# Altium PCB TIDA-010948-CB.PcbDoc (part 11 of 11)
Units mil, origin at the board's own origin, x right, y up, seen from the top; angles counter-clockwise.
Board outline 8100 x 8400 mil, 8 copper layers (L01 - TOP, L02 - GND, L03 - SIG, L04 - GND, L05 - PWR, L06 - SIG, L07 - GND, L08 - BOTTOM), stack 59.656 mil thick; 711 components, 572 nets, 2646 pads, 1325 vias.
Unrouted connection lines stored in the file: 988.
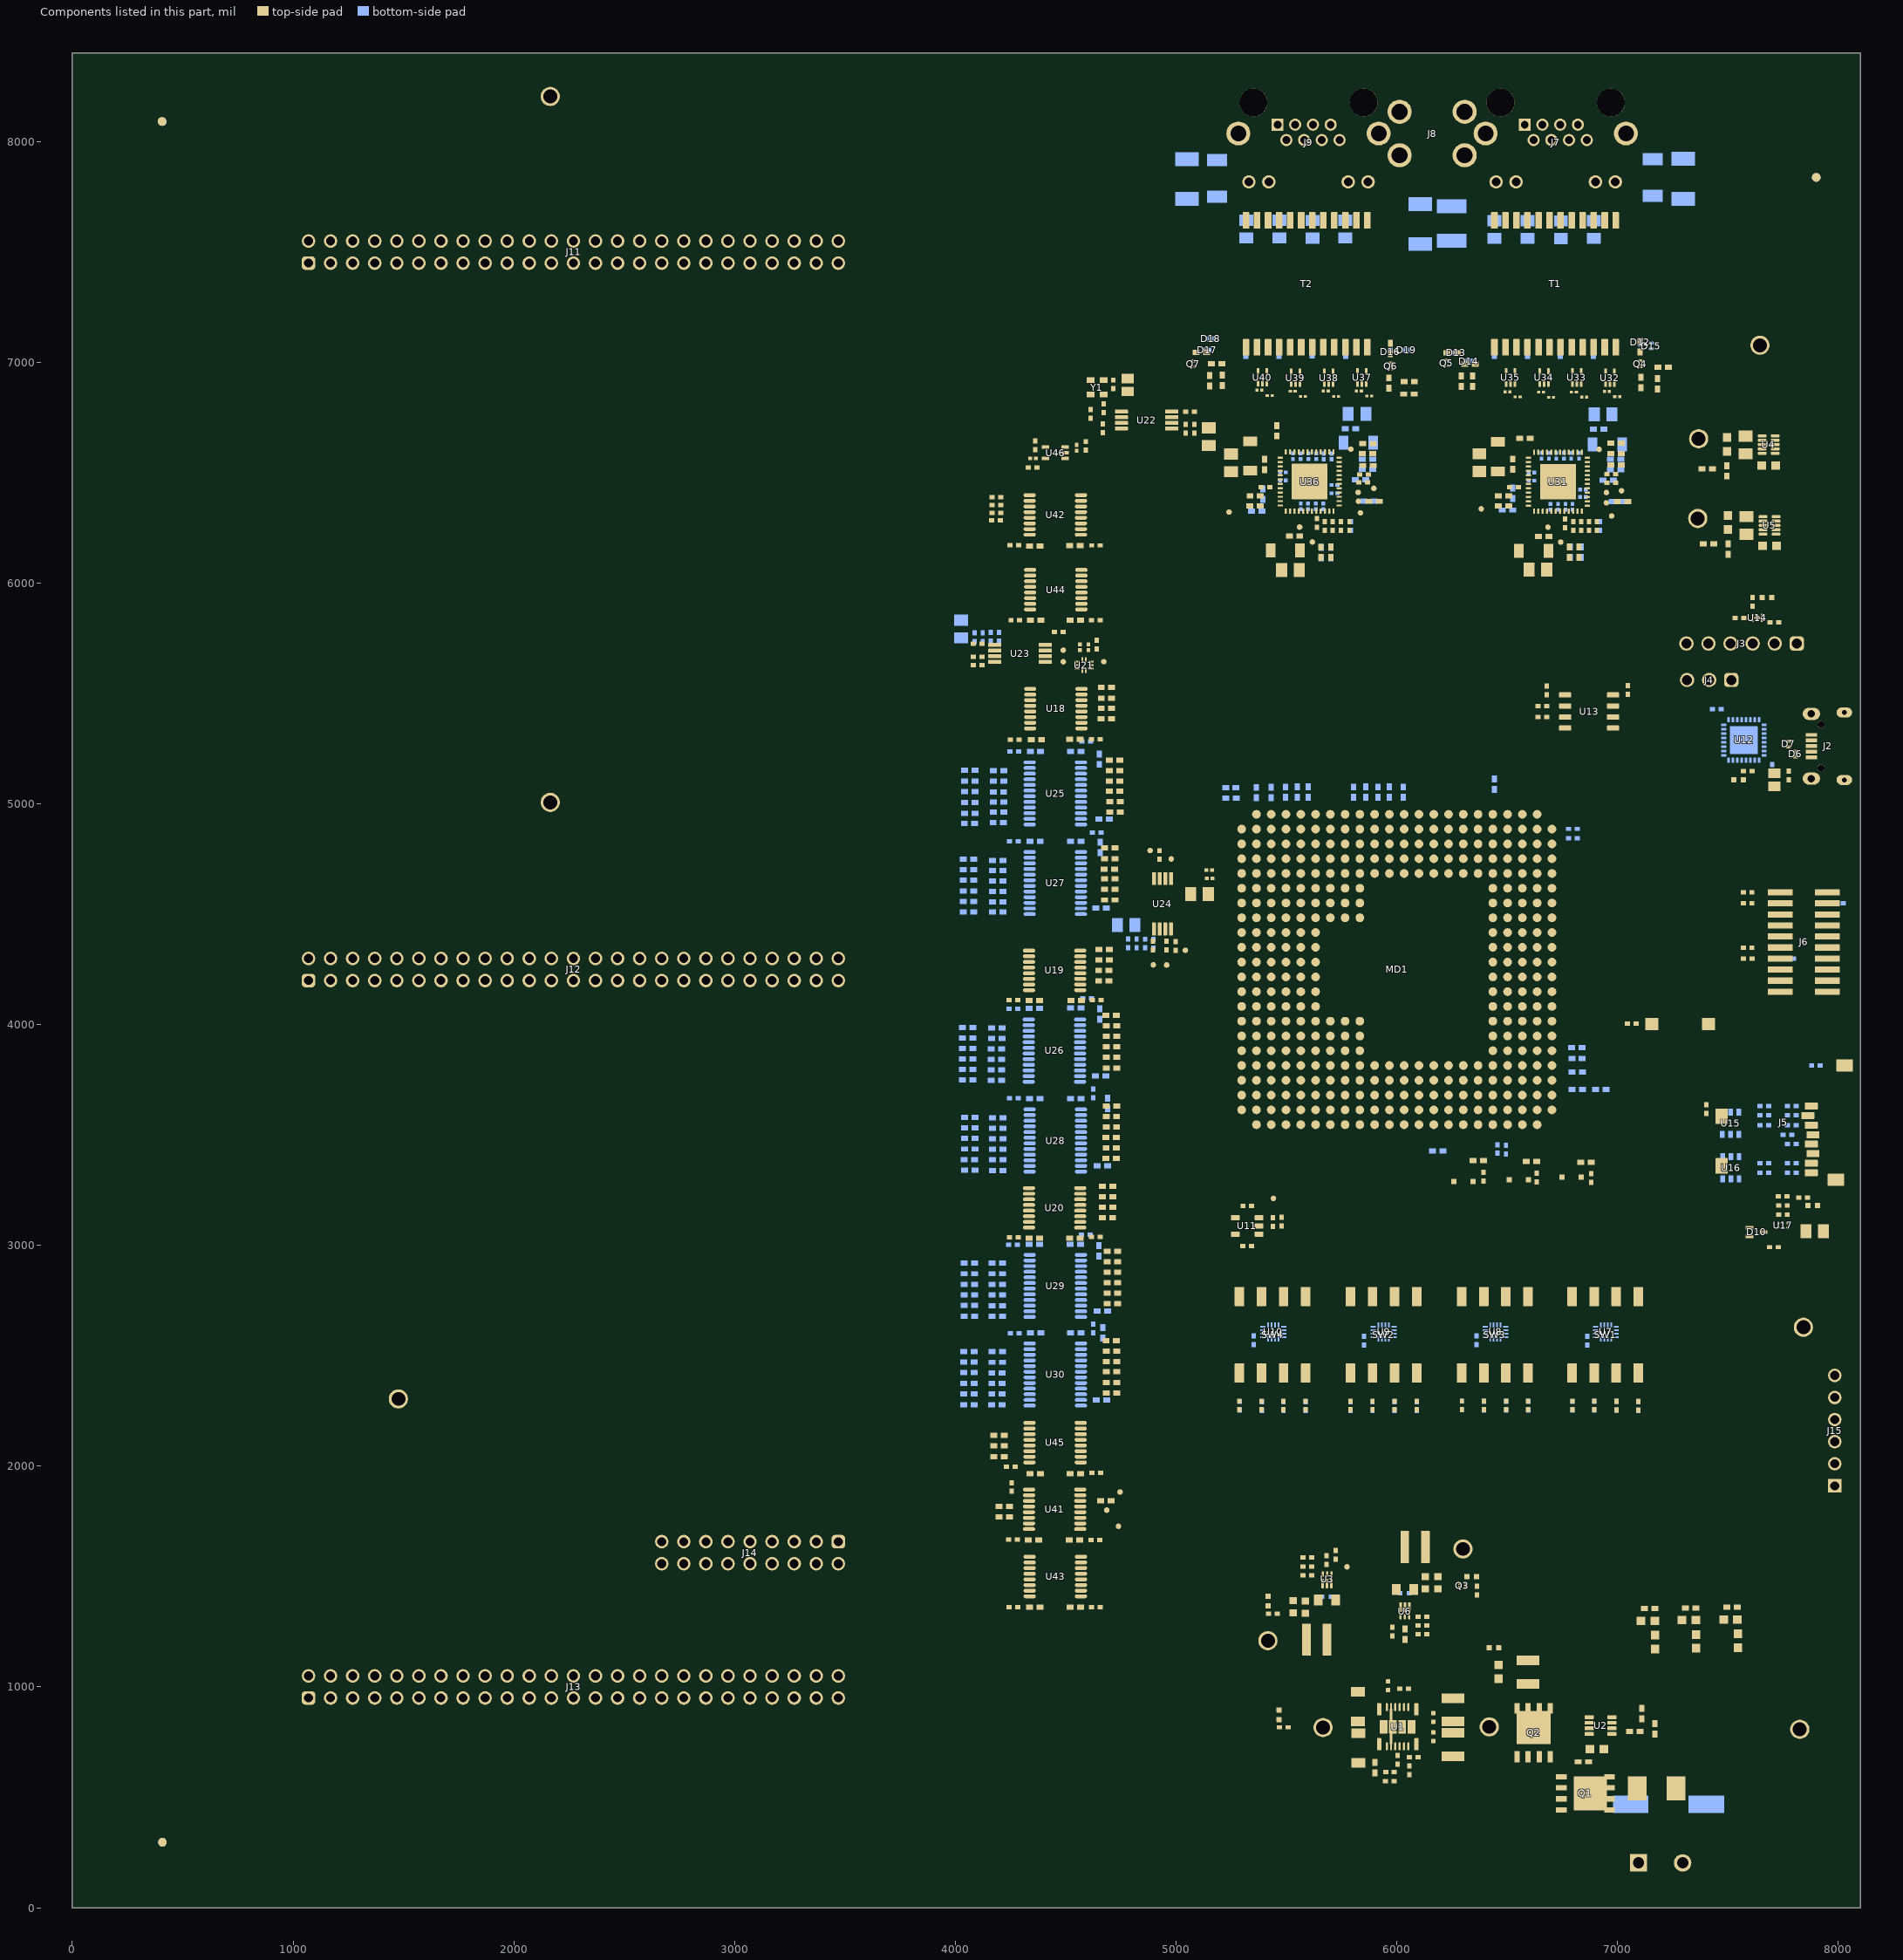
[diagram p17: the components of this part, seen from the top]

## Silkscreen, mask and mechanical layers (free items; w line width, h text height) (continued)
M12 Stackup:
  drawing of 516 lines, arcs and shapes, not listed
  text "Z0 = 50R" at 10519.74,6538.63 h35
  text "Zdiff = 100R" at 11169.35,6538.63 h35
  text "TYPE" at 9988.24,6499.26 h35
  text "line width" at 10480.37,6459.89 h35
  text "line width / space" at 11070.92,6459.89 h35
  text "LAYER 1" at 9948.87,6341.78 h35
  text "5.25 MIL" at 10519.74,6341.78 h35
  text "3.50 / 9.0 MIL" at 11149.66,6341.78 h35
  text "LAYER 2" at 9948.87,6223.67 h35
  text "---REF---" at 10480.37,6223.67 h35
  text "---REF---" at 11228.4,6223.67 h35
  text "LAYER 3" at 9948.87,6105.56 h35
  text "4.25 MIL" at 10519.74,6105.56 h35
  text "4.00 / 8.0 MIL" at 11149.66,6105.56 h35
  text "LAYER 4" at 9948.87,5987.45 h35
  text "---REF---" at 10480.37,5987.45 h35
  text "-" at 11385.88,5987.45 h35
  text "LAYER 5" at 9948.87,5869.34 h35
  text "-" at 10634.01,5869.08 h35
  text "-" at 11385.88,5869.34 h35
  text "4.25 MIL" at 10515.74,5753.06 h35
  text "LAYER 6" at 9948.87,5751.23 h35
  text "-" at 11385.88,5751.23 h35
  text "Layer" at 9901.87,5344.5 h35
  text "Name" at 10141.32,5344.5 h35
  text "Material" at 10684,5344.5 h35
  text "Thickness" at 12200.54,5344.5 h35
  text "Constant" at 12579.94,5344.5 h35
  text "Board Layer Stack" at 12912.69,5344.5 h35
  text "Top Overlay" at 10141.32,5274.5 h35
  text "Top Solder" at 10141.32,5204.5 h35
  text "Solder Resist" at 10684,5204.5 h35
  text "0.90mil" at 12200.54,5204.5 h35
  text "4.1" at 12579.94,5204.5 h35
  text "1" at 9901.87,5134.5 h35
  text "L01 - TOP" at 10141.32,5134.5 h35
  text "1.38mil" at 12200.54,5134.5 h35
  text "Dielectric 1" at 10141.32,5064.5 h35
  text "1080-FR4 370" at 10684,5064.5 h35
  text "2.80mil" at 12200.54,5064.5 h35
  text "4.1" at 12579.94,5064.5 h35
  text "2" at 9901.87,4994.5 h35
  text "L02 - GND" at 10141.32,4994.5 h35
  text "CF-004" at 10684,4994.5 h35
  text "1.20mil" at 12200.54,4994.5 h35
  text "Dielectric 2" at 10141.32,4924.5 h35
  text "FR4 370" at 10684,4924.5 h35
  text "5.00mil" at 12200.54,4924.5 h35
  text "4.1" at 12579.94,4924.5 h35
  text "3" at 9901.87,4854.5 h35
  text "L03 - SIG" at 10141.32,4854.5 h35
  text "1.20mil" at 12200.54,4854.5 h35
  text "Dielectric 3" at 10141.32,4784.5 h35
  text "1080-FR4 370 + 2116-FR4 370 + 1080-FR4 370" at 10684,4784.5 h35
  text "9.80mil" at 12200.54,4784.5 h35
  text "4.1" at 12579.94,4784.5 h35
  text "4" at 9901.87,4714.5 h35
  text "L04 - GND" at 10141.32,4714.5 h35
  text "1.20mil" at 12200.54,4714.5 h35
  text "Dielectric 4" at 10141.32,4644.5 h35
  text "FR4 370" at 10684,4644.5 h35
  text "14.50mil" at 12200.54,4644.5 h35
  text "4.4" at 12579.94,4644.5 h35
  text "5" at 9901.87,4574.5 h35
  text "L05 - PWR" at 10141.32,4574.5 h35
  text "1.20mil" at 12200.54,4574.5 h35
  text "Dielectric 5" at 10141.32,4504.5 h35
  text "1080-FR4 370 + 2116-FR4 370 + 1080-FR4 370" at 10684,4504.5 h35
  text "9.80mil" at 12200.54,4504.5 h35
  text "4.1" at 12579.94,4504.5 h35
  text "6" at 9901.87,4434.5 h35
  text "L06 - SIG" at 10141.32,4434.5 h35
  text "1.20mil" at 12200.54,4434.5 h35
  text "Dielectric 6" at 10141.32,4364.5 h35
  text "FR4 370" at 10684,4364.5 h35
  text "5.00mil" at 12200.54,4364.5 h35
  text "4.1" at 12579.94,4364.5 h35
  text "7" at 9901.87,4294.5 h35
  text "L07 - GND" at 10141.32,4294.5 h35
  text "CF-004" at 10684,4294.5 h35
  text "1.20mil" at 12200.54,4294.5 h35
  text "Dielectric 7" at 10141.32,4224.5 h35
  text "1080-FR4 370" at 10684,4224.5 h35
  text "2.80mil" at 12200.54,4224.5 h35
  text "4.1" at 12579.94,4224.5 h35
  text "8" at 9901.87,4154.5 h35
  text "L08 - BOTTOM" at 10141.32,4154.5 h35
  text "1.38mil" at 12200.54,4154.5 h35
  text "Bottom Solder" at 10141.32,4084.5 h35
  text "Solder Resist" at 10684,4084.5 h35
  text "0.90mil" at 12200.54,4084.5 h35
  text "4.1" at 12579.94,4084.5 h35
  text "Bottom Overlay" at 10141.32,4014.5 h35
  text ".Layer_Name" at 577,-558.49 h60
M13 Component Bodies Top:
  text ".Layer_Name" at 577,-558.49 h60
M14 Component Bodies Bottom:
  text ".Layer_Name" at 577,-558.49 h60
M15 Courtyards Top:
  text ".Layer_Name" at 577,-558.49 h60
M16 Courtyards Bottom:
  text ".Layer_Name" at 577,-558.49 h60
Drill Drawing:
  drawing of 184 lines, arcs and shapes, not listed
  text "Symbol" at 15205.91,5542.5 h42
  text "Quantity" at 15498.34,5542.5 h42
  text "Finished Hole Size" at 15875.74,5542.5 h42
  text "Plated" at 16658,5542.5 h42
  text "Hole Type" at 16950.43,5542.5 h42
  text "Drill Layer Pair" at 17375.82,5542.5 h42
  text "Hole Tolerance" at 18260.55,5542.5 h42
  text "2" at 15498.34,5455 h35
  text "31.50mil (0.800mm)" at 15875.74,5455 h35
  text "NPTH" at 16658,5455 h35
  text "Round" at 16950.43,5455 h35
  text "L01 - TOP - L08 - BOTTOM" at 17375.82,5455 h35
  text "4" at 15498.34,5367.5 h35
  text "125.98mil (3.200mm)" at 15875.74,5367.5 h35
  text "NPTH" at 16658,5367.5 h35
  text "Round" at 16950.43,5367.5 h35
  text "L01 - TOP - L08 - BOTTOM" at 17375.82,5367.5 h35
  text "1317" at 15498.34,5280 h35
  text "7.87mil (0.200mm)" at 15875.74,5280 h35
  text "PTH" at 16658,5280 h35
  text "Round" at 16950.43,5280 h35
  text "L01 - TOP - L08 - BOTTOM" at 17375.82,5280 h35
  text "2" at 15498.34,5192.5 h35
  text "8.00mil (0.203mm)" at 15875.74,5192.5 h35
  text "PTH" at 16658,5192.5 h35
  text "Round" at 16950.43,5192.5 h35
  text "L01 - TOP - L08 - BOTTOM" at 17375.82,5192.5 h35
  text "B" at 15189.51,5187.5 h38.89
  text "16" at 15498.34,5105 h35
  text "35.43mil (0.900mm)" at 15875.74,5105 h35
  text "PTH" at 16658,5105 h35
  text "Round" at 16950.43,5105 h35
  text "L01 - TOP - L08 - BOTTOM" at 17375.82,5105 h35
  text "8" at 15498.34,5017.5 h35
  text "39.37mil (1.000mm)" at 15875.74,5017.5 h35
  text "PTH" at 16658,5017.5 h35
  text "Round" at 16950.43,5017.5 h35
  text "L01 - TOP - L08 - BOTTOM" at 17375.82,5017.5 h35
  text "6" at 15498.34,4930 h35
  text "40.00mil (1.016mm)" at 15875.74,4930 h35
  text "PTH" at 16658,4930 h35
  text "Round" at 16950.43,4930 h35
  text "L01 - TOP - L08 - BOTTOM" at 17375.82,4930 h35
  text "168" at 15498.34,4842.5 h35
  text "40.16mil (1.020mm)" at 15875.74,4842.5 h35
  text "PTH" at 16658,4842.5 h35
  text "Round" at 16950.43,4842.5 h35
  text "L01 - TOP - L08 - BOTTOM" at 17375.82,4842.5 h35
  text "9" at 15498.34,4755 h35
  text "45.28mil (1.150mm)" at 15875.74,4755 h35
  text "PTH" at 16658,4755 h35
  text "Round" at 16950.43,4755 h35
  text "L01 - TOP - L08 - BOTTOM" at 17375.82,4755 h35
  text "2" at 15498.34,4667.5 h35
  text "51.18mil (1.300mm)" at 15875.74,4667.5 h35
  text "PTH" at 16658,4667.5 h35
  text "Round" at 16950.43,4667.5 h35
  text "L01 - TOP - L08 - BOTTOM" at 17375.82,4667.5 h35
  text "12" at 15498.34,4580 h35
  text "63.00mil (1.600mm)" at 15875.74,4580 h35
  text "PTH" at 16658,4580 h35
  text "Round" at 16950.43,4580 h35
  text "L01 - TOP - L08 - BOTTOM" at 17375.82,4580 h35
  text "4" at 15498.34,4492.5 h35
  text "70.87mil (1.800mm)" at 15875.74,4492.5 h35
  text "PTH" at 16658,4492.5 h35
  text "Round" at 16950.43,4492.5 h35
  text "L01 - TOP - L08 - BOTTOM" at 17375.82,4492.5 h35
  text "4" at 15498.34,4405 h35
  text "72.84mil (1.850mm)" at 15875.74,4405 h35
  text "PTH" at 16658,4405 h35
  text "Round" at 16950.43,4405 h35
  text "L01 - TOP - L08 - BOTTOM" at 17375.82,4405 h35
  text "+/-1.97mil" at 18260.55,4405 h35
  text "6" at 15498.34,4317.5 h35
  text "144.00mil (3.658mm)" at 15875.74,4317.5 h35
  text "PTH" at 16658,4317.5 h35
  text "Round" at 16950.43,4317.5 h35
  text "L01 - TOP - L08 - BOTTOM" at 17375.82,4317.5 h35
  text "+/-3.00mil" at 18260.55,4317.5 h35
  text "2" at 15498.34,4230 h35
  text "21.65mil (0.550mm)" at 15875.74,4230 h35
  text "PTH" at 16658,4230 h35
  text "Slot" at 16950.43,4230 h35
  text "L01 - TOP - L08 - BOTTOM" at 17375.82,4230 h35
  text "2" at 15498.34,4142.5 h35
  text "33.47mil (0.850mm)" at 15875.74,4142.5 h35
  text "PTH" at 16658,4142.5 h35
  text "Slot" at 16950.43,4142.5 h35
  text "L01 - TOP - L08 - BOTTOM" at 17375.82,4142.5 h35
  text "1564 Total" at 15498.34,4055 h35
  text "Slot definitions :" at 15205.91,3972.1 h35
  text "Routed Path Length" at 15805.98,3972.1 h35
  text "= Calculated from tool start centre position to tool end centre position." at 16446.87,3972.1 h35
  text "Hole Length" at 15805.98,3915.44 h35
  text "= Routed Path Length + Tool Size = Slot length as defined in the PCB layout" at 16207.78,3915.44 h35
  text ".Layer_Name" at 577,-558.49 h60
M17 Embedded Cavity:
  text ".Layer_Name" at 577,-558.49 h60
M18 Embedded Assembly:
  text ".Layer_Name" at 577,-558.49 h60
M19 Embedded Keepout:
  text ".Layer_Name" at 577,-558.49 h60
M20 DXF-Import:
  lines w1.97: 0,2014.44 0,4140.8

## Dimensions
0,0 to 0,8400 on M2 Board Dimensions
8100,-8 to 0,8400 on M2 Board Dimensions
8656,-405 to 9656,-405 on M2 Board Dimensions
